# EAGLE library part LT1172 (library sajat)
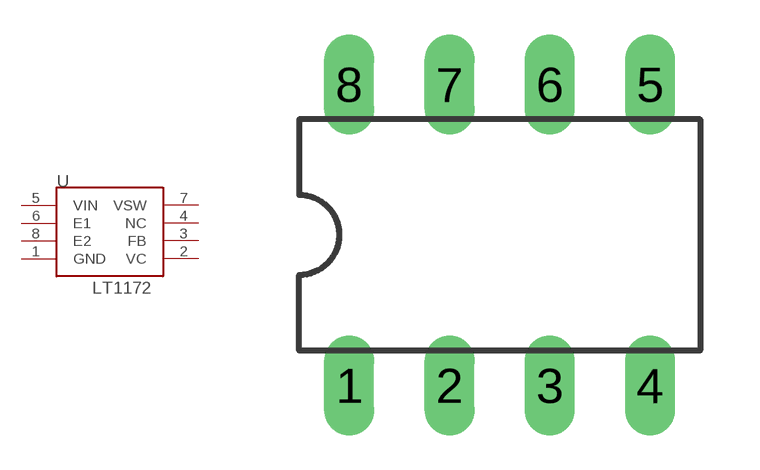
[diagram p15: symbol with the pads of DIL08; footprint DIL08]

Designator prefix -

## LT1172  [DIL08]
1  GND
2  VC
3  FB
4  NC
5  VIN
6  E1
7  VSW
8  E2

## Footprint DIL08 (pad centres in mm)
Dual In Line Package
drill 0.5 pad 1.27 long: 1 -3.81,-3.81; 2 -1.27,-3.81; 3 1.27,-3.81; 4 3.81,-3.81; 5 3.81,3.81; 6 1.27,3.81; 7 -1.27,3.81; 8 -3.81,3.81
